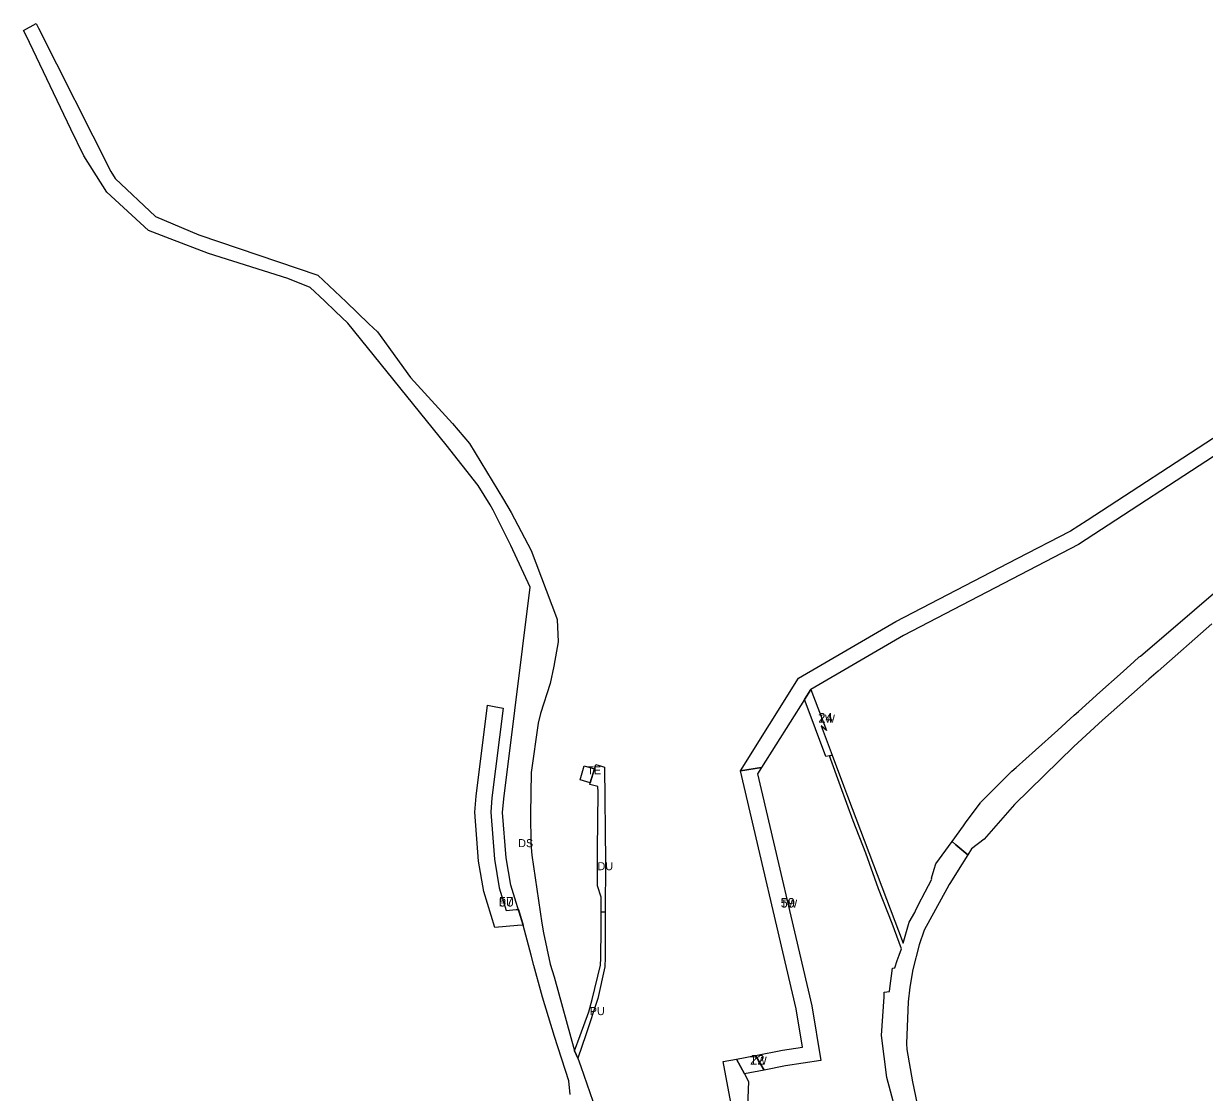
# Model space of a CAD drawing. Extents: x -519992 to -518210, y -1182334 to -1179965.
# Drawn here: x -519992 to -519254, y -1180633 to -1179965 of the extents above; entities that cross this region are included whole.
import ezdxf

# ---------------------------------------------------------------- set-up
doc = ezdxf.new("R2010")
doc.units = 0
for name, color, linetype in [('90310013', 7, 'Continuous'), ('90320013', 7, 'Continuous'), ('90390023', 7, 'Continuous'), ('90400013', 7, 'Continuous'), ('90450013', 7, 'Continuous'), ('90450023', 7, 'Continuous'), ('ID_navrh', 7, 'Continuous')]:
    doc.layers.add(name, color=color, linetype=linetype)

msp = doc.modelspace()

# ---------------------------------------------------------------- linework, layer by layer
at = {"layer": '90310013'}
msp.add_lwpolyline([(-519632.85, -1180441.9), (-519637.935, -1180440.595), (-519637.6, -1180439.47), (-519635.01, -1180430.78), (-519634.228, -1180428.155), (-519630.58, -1180429.19), (-519628.77, -1180429.69), (-519628.15, -1180488.9), (-519628.28, -1180520.14), (-519630.85, -1180520.26), (-519630.86, -1180510.85), (-519633.14, -1180503.86), (-519633.03, -1180481.47), (-519632.79, -1180445.37)], close=True, dxfattribs=at)
at = {"layer": '90320013'}
for points in [[(-519650.1, -1180634.22), (-519650.98, -1180625.68), (-519660.08, -1180597.91), (-519667.42, -1180573.37), (-519668.07, -1180571.07), (-519672.84, -1180553.61), (-519674.54, -1180547.09), (-519679.53, -1180528.4), (-519687.23, -1180503.42), (-519690.13, -1180486.31), (-519692.37, -1180457.96), (-519691.65, -1180449.59), (-519684.8, -1180394.392), (-519675.24, -1180317.36), (-519687.23, -1180291.23), (-519698.4, -1180269.26), (-519700.26, -1180265.82), (-519707.67, -1180253.78), (-519727.7, -1180228.32), (-519789.06, -1180152.46), (-519796.828, -1180145.039), (-519803.64, -1180138.53), (-519812.65, -1180130.15), (-519826.58, -1180124.53), (-519876.16, -1180108.79), (-519900.11, -1180099.8), (-519913.72, -1180094.56), (-519939.79, -1180070.47), (-519954.08, -1180047.91), (-519962.14, -1180031.22), (-519990.22, -1179972.72), (-519991.72, -1179969.54), (-519983.9, -1179965.28), (-519982.32, -1179968.2), (-519937.13, -1180057.7), (-519934.55, -1180062.12), (-519909.38, -1180085.67), (-519882.18, -1180097.21), (-519807.85, -1180122.32), (-519790.242, -1180139.09), (-519775.91, -1180152.74), (-519770.6, -1180157.73), (-519749.89, -1180186.34), (-519723.65, -1180215.01), (-519713.02, -1180227.59), (-519691.85, -1180262.63), (-519686.99, -1180270.61), (-519674.66, -1180294.35), (-519658.78, -1180336.26), (-519658.29, -1180337.55), (-519657.79, -1180351.37), (-519660.39, -1180366.6), (-519662.6, -1180377.38), (-519668.67, -1180396.26), (-519670.2, -1180402.27), (-519674.65, -1180433.04), (-519674.98, -1180459.02), (-519674.81, -1180477.49), (-519674.05, -1180484.63), (-519670.07, -1180513.08), (-519667.818, -1180527.22), (-519666.88, -1180533.11), (-519662.64, -1180552.73), (-519660.09, -1180560.72), (-519647.49, -1180606.85), (-519645.43, -1180611.45), (-519643.53, -1180616.69), (-519635.98, -1180638.42)], [(-519249.16, -1180340.26), (-519282.81, -1180369.73), (-519288.55, -1180374.8), (-519317.6, -1180400.45), (-519335.47, -1180416.78), (-519372.45, -1180453), (-519391.52, -1180474.74), (-519399.4, -1180480.67), (-519401.789, -1180484.508), (-519409.19, -1180478.29), (-519411.56, -1180476.2), (-519404.46, -1180466.41), (-519402.68, -1180463.97), (-519393.86, -1180451.93), (-519393.56, -1180451.65), (-519383.14, -1180441.22), (-519374.1, -1180432.17), (-519371.54, -1180429.87), (-519359.51, -1180419.1), (-519345.54, -1180406.59), (-519335.21, -1180397.34), (-519332.64, -1180395.04), (-519319.18, -1180382.98), (-519306.52, -1180371.63), (-519297.95, -1180363.96), (-519294.53, -1180360.9), (-519293.87, -1180360.31), (-519259.97, -1180331.39), (-519233.45, -1180308.61)]]:
    msp.add_lwpolyline(points, dxfattribs=at)
at = {"layer": '90390023'}
for points in [[(-519530.579, -1180429.847), (-519543.828, -1180432.113), (-519507.413, -1180374.043), (-519446.618, -1180338.797), (-519370.805, -1180299.397), (-519337.818, -1180282.254), (-519337.72, -1180282.23), (-519337.489, -1180282.083), (-519327.14, -1180275.48), (-519244.032, -1180221.205), (-519222.249, -1180206.979), (-519186.97, -1180183.94), (-519171.27, -1180171.17), (-519011.96, -1179982.64), (-519010.33, -1179980.49), (-519006.122, -1179991.224), (-519164.235, -1180178.338), (-519181.068, -1180192.03), (-519220.038, -1180217.438), (-519238.561, -1180229.516), (-519332.465, -1180290.741), (-519441.802, -1180347.563), (-519499.747, -1180381.157), (-519503.729, -1180387.445)], [(-519499.747, -1180381.157), (-519489.994, -1180406.887), (-519493.42, -1180403.86), (-519486.466, -1180422.3), (-519488.1, -1180422.58), (-519490.35, -1180422.965), (-519503.318, -1180388.536), (-519503.729, -1180387.445)], [(-519543.828, -1180432.113), (-519530.579, -1180429.847), (-519533.139, -1180433.891), (-519499.15, -1180578.715), (-519493.512, -1180612.957), (-519515.711, -1180616.366), (-519529.021, -1180618.912), (-519534.35, -1180609.75), (-519517.41, -1180606.51), (-519505.021, -1180604.607), (-519508.963, -1180580.672)], [(-519534.35, -1180609.75), (-519529.021, -1180618.912), (-519541.304, -1180621.261), (-519546.312, -1180612.038), (-519546.312, -1180612.038)]]:
    msp.add_lwpolyline(points, close=True, dxfattribs=at)
msp.add_lwpolyline([(-519548.528, -1180645.8), (-519554.552, -1180613.614), (-519546.312, -1180612.038), (-519541.304, -1180621.261), (-519538.72, -1180626.02), (-519539.34, -1180641.78)], dxfattribs=at)
at = {"layer": '90400013'}
msp.add_lwpolyline([(-519641.53, -1180428.92), (-519635.01, -1180430.78), (-519637.6, -1180439.47), (-519643.95, -1180437.67)], close=True, dxfattribs=at)
at = {"layer": '90450013'}
msp.add_lwpolyline([(-519444.65, -1180652.26), (-519452.21, -1180623.57), (-519455.66, -1180597.28), (-519453.95, -1180573.29), (-519454.03, -1180570.32), (-519450.58, -1180569.86), (-519450.48, -1180568.08), (-519448.8, -1180555.21), (-519447.22, -1180555.01), (-519445.79, -1180550.4), (-519444.59, -1180547.12), (-519443.22, -1180543.16), (-519449, -1180527.32), (-519457.44, -1180505.68), (-519465.52, -1180483.4), (-519473.36, -1180463.3), (-519481.34, -1180441.52), (-519488.1, -1180422.58), (-519486.466, -1180422.3), (-519479.35, -1180441.17), (-519476.87, -1180447.79), (-519442.18, -1180539.68), (-519438.26, -1180526.55), (-519434.71, -1180520.43), (-519433.88, -1180518.47), (-519430.62, -1180512.07), (-519430.38, -1180511.59), (-519424.29, -1180499.77), (-519424.44, -1180499.15), (-519422.66, -1180493.35), (-519421.7, -1180490.19), (-519411.56, -1180476.2), (-519409.19, -1180478.29), (-519401.789, -1180484.508), (-519407.78, -1180494.13), (-519412.524, -1180501.733), (-519413.32, -1180503.01), (-519414.86, -1180505.83), (-519428.93, -1180531.5), (-519432.18, -1180540.62), (-519435.97, -1180556.03), (-519437.98, -1180567.11), (-519439.02, -1180576.21), (-519440.08, -1180602.36), (-519439.81, -1180606.18), (-519436.32, -1180626.33), (-519432.39, -1180645.23)], dxfattribs=at)
msp.add_lwpolyline([(-519645.43, -1180611.45), (-519647.49, -1180606.85), (-519643.86, -1180597.34), (-519638.58, -1180582.52), (-519636.38, -1180574.78), (-519631.17, -1180553.45), (-519631.09, -1180548.95), (-519630.81, -1180530.53), (-519630.85, -1180520.26), (-519628.28, -1180520.14), (-519628.3, -1180548.57), (-519628.57, -1180554.5), (-519632.93, -1180574.33), (-519640.49, -1180596.89)], close=True, dxfattribs=at)
at = {"layer": '90450023'}
msp.add_lwpolyline([(-519701.937, -1180390.984), (-519697.727, -1180391.821), (-519692.103, -1180392.94), (-519699.038, -1180448.814), (-519699.822, -1180457.934), (-519697.508, -1180487.225), (-519694.471, -1180505.142), (-519690.126, -1180519.236), (-519683.897, -1180518.67), (-519682.557, -1180518.58), (-519679.53, -1180528.4), (-519683.11, -1180528.64), (-519697.295, -1180529.929), (-519704.221, -1180507.46), (-519707.442, -1180488.457), (-519709.856, -1180457.899), (-519708.985, -1180447.769)], close=True, dxfattribs=at)

# ---------------------------------------------------------------- texts
at = {"layer": '90310013'}
msp.add_text('DU', height=5, dxfattribs=at).set_placement((-519633.0425, -1180494.0866))
at = {"layer": '90320013'}
msp.add_text('DS', height=5, rotation=360, dxfattribs=at).set_placement((-519682.6151, -1180479.683))
at = {"layer": '90390023'}
for rotation, p in [(0.0000001, (-519495.0975, -1180401.892)), (0, (-519518.67, -1180517.4264)), (360, (-519537.7158, -1180615.5055))]:
    msp.add_text('TW', height=5, rotation=rotation, dxfattribs=at).set_placement(p)
at = {"layer": '90400013'}
msp.add_text('TE', height=5, rotation=0, dxfattribs=at).set_placement((-519639.48, -1180434.221))
at = {"layer": '90450013'}
msp.add_text('PU', height=5, rotation=0, dxfattribs=at).set_placement((-519637.885, -1180584.5956))
at = {"layer": '90450023'}
msp.add_text('PU', height=5, rotation=360, dxfattribs=at).set_placement((-519694.693, -1180516.7624))
at = {"layer": 'ID_navrh'}
for s, rotation, p in [('24', 0, (-519495.0975, -1180401.892)), ('57', 360, (-519694.693, -1180516.7624)), ('59', 360, (-519518.67, -1180517.4264)), ('22', 360, (-519537.7158, -1180615.5055))]:
    msp.add_text(s, height=6, rotation=rotation, dxfattribs=at).set_placement(p)

doc.saveas('drawing.dxf')
